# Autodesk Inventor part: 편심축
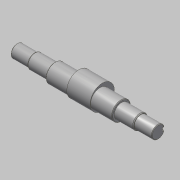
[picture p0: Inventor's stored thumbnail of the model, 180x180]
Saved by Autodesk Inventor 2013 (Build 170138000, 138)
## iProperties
Created: 2015-10
Part Number: 편심축
Document SubType Name: Modeling
Designer: mdu
Density: 7.86 g/cm^3
Material: 강철, 연강
Mass: 1327.14 g
Surface Area: 247.481 cm^2
Volume: 168.848 cm^3
Author: mdu
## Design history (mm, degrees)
sketch "스케치1"
  geometry: L1 (-20.5, -41.331)-(-20.5, 32.669) reference; L2 (7.5, -30.031)-(7.5, 21.369) reference; L3 (135.5, -30.331)-(135.5, 21.669) reference; L4 (121.5, 21.369)-(121.5, -30.031) reference; L5 (184.5, -4.331)-(-57.5, -4.331); L6 (184.5, -4.331)-(184.5, 6.669); L7 (154.5, 8.169)-(121.5, 8.169); L8 (121.5, 8.169)-(121.5, 11.669); L9 (121.5, 11.669)-(7.5, 11.669); L10 (7.5, 11.669)-(7.5, 8.169); L11 (7.5, 8.169)-(-27.5, 8.169); L12 (-27.5, 8.169)-(-27.5, 6.669); L13 (-27.5, 6.669)-(-57.5, 6.669); L14 (-57.5, 6.669)-(-57.5, -4.331); L15 (154.5, 8.169)-(154.5, 6.669); L16 (154.5, 6.669)-(184.5, 6.669); C1 r 32.5 at (64.5, -4.331) reference; 1 further point
  constraints: 24 end point, 8 perpendicular, 5 point on line, 3 parallel, 2 collinear
  dimensions: "d1" = 25 diameter of L11 L5; "d2" = 32 diameter of L9 L5; "d3" = 22 diameter of L13 L5; "d4" = 35 distance of L10.end L11.end; "d5" = 30 distance of L12.end L13.end; "d15" = 33 distance of L7.start L7.end; "d26" = 30 distance of L15.end L6.end
revolve "회전1" sketch "스케치1" stored, may be unused: angle "d6" = 90 deg
node "작업 평면1"
sketch "스케치2"
  geometry: C1 r 16 at (0, 0) reference; C2 r 16 at (0, 0) reference; C3 r 20.75 at (0, 4); C4 r 16 at (0, 0) reference; 1 further point
  constraints: 1 centre point, 1 vertical alignment
  dimensions: "d8" = 41.5 diameter of C3; "d25" = 4 distance of C3.centre C1.centre
extrude "돌출1" join sketch "스케치2" stored distance "d9" = 40; taper "d10" = 0 deg
chamfer "모따기1" distance "d11" = 1; stored, may be unused: second distance "d12" = 2, angle "d13" = 45 deg
node "작업 평면2"
sketch "스케치3"
  geometry: L1 (-15, -10)-(-15, 10) reference; L2 (-15, 3)-(0, 3); L3 (0, -3)-(-15, -3); A1 r 3 centre (0, 0) between (0, -3) and (0, 3); 2 further points
  constraints: 4 end point, 2 perpendicular, 2 point on circle, 2 point on line, 2 tangent, 1 centre point, 1 horizontal alignment, 1 midpoint
  dimensions: "d16" = 18 dimension on A1 L1; "d17" = 6 distance between parallel lines of L3 L2
extrude "돌출2" cut sketch "스케치3" distance "d18" = 3.5; taper "d19" = 0 deg
node "작업 평면3"
chamfer "모따기2" distance "d27" = 1.5; stored, may be unused: second distance "d28" = 2, angle "d29" = 30 deg
chamfer "모따기3" distance "d30" = 1.5; stored, may be unused: second distance "d31" = 2, angle "d32" = 30 deg
node "솔리드1"
mirror "대칭1"
node "참조1"
node "참조2"
node "참조3"
node "참조4"
node "참조5"
node "투영된 루프1"
